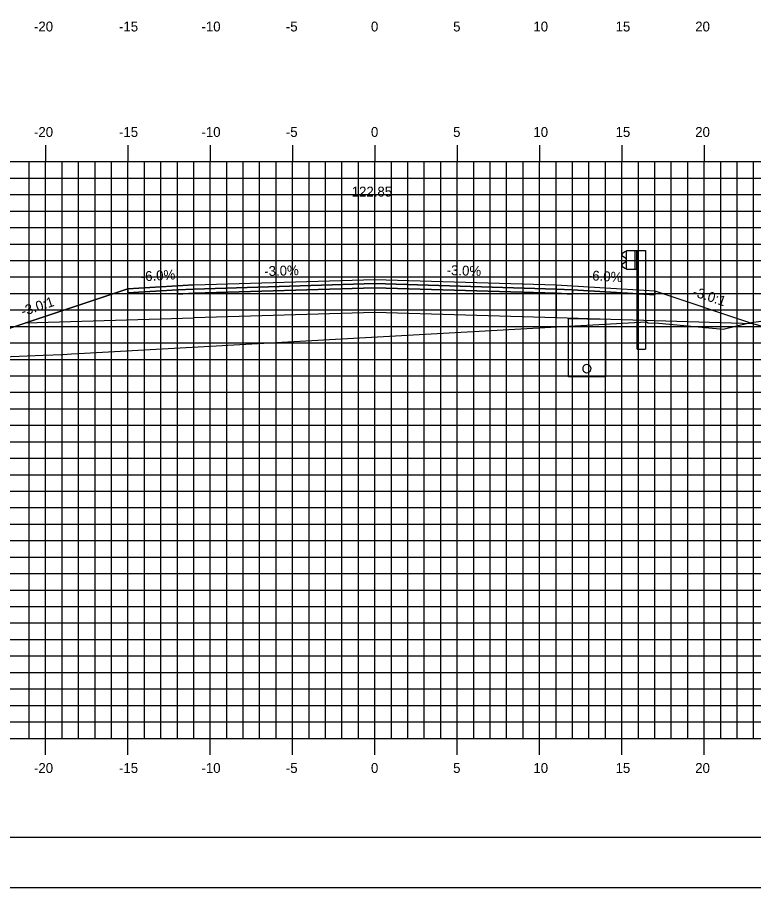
# Model space of a CAD drawing. Extents: x 850598 to 870284, y 366541 to 366651.
# Drawn here: x 855507.8 to 855552.5, y 366541.2 to 366594 of the extents above; entities that cross this region are included whole.
import ezdxf

# ---------------------------------------------------------------- set-up
doc = ezdxf.new("R2010")
doc.units = 0
for name, color, linetype in [('ANNOTATION', 7, 'Continuous'), ('BORDER', 7, 'Continuous'), ('D_Drainage_Underdrain', 7, 'Continuous'), ('D_Drainage_Underdrain_06in', 7, 'Continuous'), ('D_Guardrail_Beam_Rt', 7, 'Continuous'), ('D_Roadway_Centerline', 7, 'Continuous'), ('D_Roadway_Centerline_Text', 7, 'Continuous'), ('D_Roadway_Edge_Shoulder', 7, 'Continuous'), ('D_Roadway_Edge_TW', 7, 'Continuous'), ('D_Roadway_Pavement', 7, 'Continuous'), ('D_Roadway_SlopeLines', 7, 'Continuous'), ('D_Roadway_SubGrade', 7, 'Continuous'), ('H_V ANNOTATION', 7, 'Continuous'), ('MAJOR', 7, 'Continuous'), ('MINOR', 7, 'Continuous'), ('PLOT BOUNDARY', 7, 'Continuous'), ('S_Roadway_Centerline', 7, 'Continuous')]:
    doc.layers.add(name, color=color, linetype=linetype)

msp = doc.modelspace()

# ---------------------------------------------------------------- linework, layer by layer
at = {"layer": 'BORDER'}
msp.add_line((855484.541, 366544.225), (855644.541, 366544.225), dxfattribs=at)
at = {"layer": 'D_Drainage_Underdrain'}
msp.add_lwpolyline([(855543.541, 366575.663), (855543.541, 366572.163), (855541.291, 366572.163), (855541.291, 366575.708)], close=True, dxfattribs=at)
at = {"layer": 'D_Drainage_Underdrain_06in'}
msp.add_lwpolyline([(855542.416, 366572.913), (855542.339, 366572.901), (855542.269, 366572.865), (855542.214, 366572.81), (855542.178, 366572.74), (855542.166, 366572.663), (855542.178, 366572.586), (855542.214, 366572.516), (855542.269, 366572.461), (855542.339, 366572.425), (855542.416, 366572.413), (855542.493, 366572.425), (855542.563, 366572.461), (855542.618, 366572.516), (855542.654, 366572.586), (855542.666, 366572.663), (855542.654, 366572.74), (855542.618, 366572.81), (855542.563, 366572.865), (855542.493, 366572.901)], close=True, dxfattribs=at)
at = {"layer": 'D_Guardrail_Beam_Rt'}
for p, q in [((855544.812, 366579.764), (855544.738, 366579.751)), ((855544.812, 366579.839), (855545.499, 366579.839)), ((855544.812, 366578.672), (855544.812, 366579.839)), ((855545.333, 366579.839), (855545.333, 366578.672)), ((855545.437, 366579.839), (855545.437, 366578.672)), ((855545.499, 366579.839), (855545.97, 366579.839)), ((855545.499, 366579.839), (855545.499, 366578.672)), ((855545.97, 366579.839), (855545.97, 366573.839)), ((855544.722, 366579.745), (855544.578, 366579.645)), ((855544.578, 366579.501), (855544.774, 366579.365)), ((855544.807, 366579.301), (855544.807, 366579.21)), ((855544.774, 366579.146), (855544.578, 366579.009)), ((855544.578, 366578.866), (855544.722, 366578.766)), ((855544.738, 366578.759), (855544.812, 366578.747)), ((855545.499, 366578.672), (855544.812, 366578.672)), ((855545.478, 366573.839), (855545.478, 366578.672)), ((855545.478, 366573.839), (855545.97, 366573.839))]:
    msp.add_line(p, q, dxfattribs=at)
for centre, major_axis, start_param, end_param in [((855544.746, 366579.711), (-0.0417, 0), 4.886922, 5.323254), ((855544.629, 366579.573), (-0.0877, 0), 5.323254, 7.243116), ((855544.728, 366579.301), (0.0789, 0), 0, 0.959931), ((855544.629, 366578.938), (-0.0877, 0), 5.323254, 7.243116), ((855544.746, 366578.8), (-0.0417, 0), 0.959931, 1.396263), ((855544.728, 366579.21), (0.0789, 0), 5.323254, 6.283185)]:
    msp.add_ellipse(centre, major_axis=major_axis, ratio=0.995501, start_param=start_param, end_param=end_param, dxfattribs=at)
at = {"layer": 'D_Roadway_Centerline'}
msp.add_lwpolyline([(855501.476, 366573.15), (855504.541, 366574.172), (855508.343, 366575.439), (855514.541, 366577.505), (855518.541, 366577.745), (855529.541, 366578.075), (855540.541, 366577.745), (855544.541, 366577.505), (855546.541, 366577.385), (855552.541, 366575.385), (855599.435, 366563.225), (855612.711, 366559.783), (855622.573, 366557.225), (855626.573, 366557.225)], dxfattribs=at)
at = {"layer": 'D_Roadway_Edge_Shoulder'}
for points in [[(855518.541, 366577.745), (855514.541, 366577.505), (855514.541, 366577.255), (855517.541, 366577.435), (855518.541, 366577.495)], [(855540.541, 366577.745), (855544.541, 366577.505), (855544.541, 366577.505), (855546.541, 366577.385), (855546.541, 366577.135), (855541.541, 366577.435), (855540.541, 366577.495)]]:
    msp.add_lwpolyline(points, close=True, dxfattribs=at)
at = {"layer": 'D_Roadway_Edge_TW'}
msp.add_lwpolyline([(855518.541, 366577.495), (855518.541, 366577.745), (855529.541, 366578.075), (855540.541, 366577.745), (855540.541, 366577.495), (855529.541, 366577.825)], close=True, dxfattribs=at)
at = {"layer": 'D_Roadway_Pavement'}
for points in [[(855518.541, 366577.245), (855518.541, 366577.495), (855529.541, 366577.825), (855540.541, 366577.495), (855540.541, 366577.245), (855529.541, 366577.575)], [(855518.541, 366577.495), (855517.541, 366577.435), (855517.541, 366577.185), (855518.541, 366577.245)], [(855540.541, 366577.495), (855541.541, 366577.435), (855541.541, 366577.185), (855540.541, 366577.245)]]:
    msp.add_lwpolyline(points, close=True, dxfattribs=at)
at = {"layer": 'D_Roadway_SlopeLines'}
msp.add_lwpolyline([(855518.541, 366577.745), (855514.541, 366577.505), (855504.541, 366574.172)], dxfattribs=at)
at = {"layer": 'D_Roadway_SubGrade'}
for points in [[(855518.541, 366577.245), (855517.541, 366577.185), (855517.541, 366577.435), (855514.541, 366577.255), (855514.541, 366577.505), (855508.343, 366575.439), (855518.541, 366575.745)], [(855518.541, 366575.745), (855518.541, 366577.245), (855529.541, 366577.575), (855540.541, 366577.245), (855540.541, 366575.745), (855529.541, 366576.075)], [(855540.541, 366577.245), (855541.541, 366577.185), (855541.541, 366577.435), (855546.541, 366577.135), (855546.541, 366577.385), (855552.541, 366575.385), (855540.541, 366575.745)]]:
    msp.add_lwpolyline(points, close=True, dxfattribs=at)
at = {"layer": 'MAJOR'}
for p, q in [((855509.541, 366586.227), (855509.541, 366585.225)), ((855509.541, 366586.227), (855509.541, 366585.225)), ((855514.541, 366586.227), (855514.541, 366585.225)), ((855514.541, 366586.227), (855514.541, 366585.225)), ((855519.541, 366586.227), (855519.541, 366585.225)), ((855519.541, 366586.227), (855519.541, 366585.225)), ((855524.541, 366586.227), (855524.541, 366585.225)), ((855524.541, 366586.227), (855524.541, 366585.225)), ((855529.541, 366586.227), (855529.541, 366585.225)), ((855529.541, 366586.227), (855529.541, 366585.225)), ((855534.541, 366586.227), (855534.541, 366585.225)), ((855534.541, 366586.227), (855534.541, 366585.225)), ((855539.541, 366586.227), (855539.541, 366585.225)), ((855539.541, 366586.227), (855539.541, 366585.225)), ((855544.541, 366586.227), (855544.541, 366585.225)), ((855544.541, 366586.227), (855544.541, 366585.225)), ((855549.541, 366586.227), (855549.541, 366585.225)), ((855549.541, 366586.227), (855549.541, 366585.225)), ((855489.541, 366585.225), (855629.541, 366585.225)), ((855489.541, 366585.225), (855629.541, 366585.225)), ((855489.541, 366585.225), (855629.541, 366585.225)), ((855489.541, 366585.225), (855629.541, 366585.225)), ((855509.541, 366550.225), (855509.541, 366585.225)), ((855509.541, 366550.225), (855509.541, 366585.225)), ((855514.541, 366550.225), (855514.541, 366585.225)), ((855514.541, 366550.225), (855514.541, 366585.225)), ((855519.541, 366550.225), (855519.541, 366585.225)), ((855519.541, 366550.225), (855519.541, 366585.225)), ((855524.541, 366550.225), (855524.541, 366585.225)), ((855524.541, 366550.225), (855524.541, 366585.225)), ((855529.541, 366550.225), (855529.541, 366585.225)), ((855529.541, 366550.225), (855529.541, 366585.225)), ((855534.541, 366550.225), (855534.541, 366585.225)), ((855534.541, 366550.225), (855534.541, 366585.225)), ((855539.541, 366550.225), (855539.541, 366585.225)), ((855539.541, 366550.225), (855539.541, 366585.225)), ((855544.541, 366550.225), (855544.541, 366585.225)), ((855544.541, 366550.225), (855544.541, 366585.225)), ((855549.541, 366550.225), (855549.541, 366585.225)), ((855549.541, 366550.225), (855549.541, 366585.225)), ((855489.541, 366580.225), (855629.541, 366580.225)), ((855489.541, 366580.225), (855629.541, 366580.225)), ((855489.541, 366575.225), (855629.541, 366575.225)), ((855489.541, 366575.225), (855629.541, 366575.225)), ((855489.541, 366570.225), (855629.541, 366570.225)), ((855489.541, 366570.225), (855629.541, 366570.225)), ((855489.541, 366565.225), (855629.541, 366565.225)), ((855489.541, 366565.225), (855629.541, 366565.225)), ((855489.541, 366560.225), (855629.541, 366560.225)), ((855489.541, 366560.225), (855629.541, 366560.225)), ((855489.541, 366555.225), (855629.541, 366555.225)), ((855489.541, 366555.225), (855629.541, 366555.225)), ((855489.541, 366550.225), (855629.541, 366550.225)), ((855489.541, 366550.225), (855629.541, 366550.225)), ((855489.541, 366550.225), (855629.541, 366550.225)), ((855489.541, 366550.225), (855629.541, 366550.225)), ((855509.541, 366549.223), (855509.541, 366550.225)), ((855509.541, 366549.223), (855509.541, 366550.225)), ((855514.541, 366549.223), (855514.541, 366550.225)), ((855514.541, 366549.223), (855514.541, 366550.225)), ((855519.541, 366549.223), (855519.541, 366550.225)), ((855519.541, 366549.223), (855519.541, 366550.225)), ((855524.541, 366549.223), (855524.541, 366550.225)), ((855524.541, 366549.223), (855524.541, 366550.225)), ((855529.541, 366549.223), (855529.541, 366550.225)), ((855529.541, 366549.223), (855529.541, 366550.225)), ((855534.541, 366549.223), (855534.541, 366550.225)), ((855534.541, 366549.223), (855534.541, 366550.225)), ((855539.541, 366549.223), (855539.541, 366550.225)), ((855539.541, 366549.223), (855539.541, 366550.225)), ((855544.541, 366549.223), (855544.541, 366550.225)), ((855544.541, 366549.223), (855544.541, 366550.225)), ((855549.541, 366549.223), (855549.541, 366550.225)), ((855549.541, 366549.223), (855549.541, 366550.225))]:
    msp.add_line(p, q, dxfattribs=at)
at = {"layer": 'MINOR'}
for p, q in [((855508.541, 366550.225), (855508.541, 366585.225)), ((855508.541, 366550.225), (855508.541, 366585.225)), ((855510.541, 366550.225), (855510.541, 366585.225)), ((855510.541, 366550.225), (855510.541, 366585.225)), ((855511.541, 366550.225), (855511.541, 366585.225)), ((855511.541, 366550.225), (855511.541, 366585.225)), ((855512.541, 366550.225), (855512.541, 366585.225)), ((855512.541, 366550.225), (855512.541, 366585.225)), ((855513.541, 366550.225), (855513.541, 366585.225)), ((855513.541, 366550.225), (855513.541, 366585.225)), ((855515.541, 366550.225), (855515.541, 366585.225)), ((855515.541, 366550.225), (855515.541, 366585.225)), ((855516.541, 366550.225), (855516.541, 366585.225)), ((855516.541, 366550.225), (855516.541, 366585.225)), ((855517.541, 366550.225), (855517.541, 366585.225)), ((855517.541, 366550.225), (855517.541, 366585.225)), ((855518.541, 366550.225), (855518.541, 366585.225)), ((855518.541, 366550.225), (855518.541, 366585.225)), ((855520.541, 366550.225), (855520.541, 366585.225)), ((855520.541, 366550.225), (855520.541, 366585.225)), ((855521.541, 366550.225), (855521.541, 366585.225)), ((855521.541, 366550.225), (855521.541, 366585.225)), ((855522.541, 366550.225), (855522.541, 366585.225)), ((855522.541, 366550.225), (855522.541, 366585.225)), ((855523.541, 366550.225), (855523.541, 366585.225)), ((855523.541, 366550.225), (855523.541, 366585.225)), ((855525.541, 366550.225), (855525.541, 366585.225)), ((855525.541, 366550.225), (855525.541, 366585.225)), ((855526.541, 366550.225), (855526.541, 366585.225)), ((855526.541, 366550.225), (855526.541, 366585.225)), ((855527.541, 366550.225), (855527.541, 366585.225)), ((855527.541, 366550.225), (855527.541, 366585.225)), ((855528.541, 366550.225), (855528.541, 366585.225)), ((855528.541, 366550.225), (855528.541, 366585.225)), ((855530.541, 366550.225), (855530.541, 366585.225)), ((855530.541, 366550.225), (855530.541, 366585.225)), ((855531.541, 366550.225), (855531.541, 366585.225)), ((855531.541, 366550.225), (855531.541, 366585.225)), ((855532.541, 366550.225), (855532.541, 366585.225)), ((855532.541, 366550.225), (855532.541, 366585.225)), ((855533.541, 366550.225), (855533.541, 366585.225)), ((855533.541, 366550.225), (855533.541, 366585.225)), ((855535.541, 366550.225), (855535.541, 366585.225)), ((855535.541, 366550.225), (855535.541, 366585.225)), ((855536.541, 366550.225), (855536.541, 366585.225)), ((855536.541, 366550.225), (855536.541, 366585.225)), ((855537.541, 366550.225), (855537.541, 366585.225)), ((855537.541, 366550.225), (855537.541, 366585.225)), ((855538.541, 366550.225), (855538.541, 366585.225)), ((855538.541, 366550.225), (855538.541, 366585.225)), ((855540.541, 366550.225), (855540.541, 366585.225)), ((855540.541, 366550.225), (855540.541, 366585.225)), ((855541.541, 366550.225), (855541.541, 366585.225)), ((855541.541, 366550.225), (855541.541, 366585.225)), ((855542.541, 366550.225), (855542.541, 366585.225)), ((855542.541, 366550.225), (855542.541, 366585.225)), ((855543.541, 366550.225), (855543.541, 366585.225)), ((855543.541, 366550.225), (855543.541, 366585.225)), ((855545.541, 366550.225), (855545.541, 366585.225)), ((855545.541, 366550.225), (855545.541, 366585.225)), ((855546.541, 366550.225), (855546.541, 366585.225)), ((855546.541, 366550.225), (855546.541, 366585.225)), ((855547.541, 366550.225), (855547.541, 366585.225)), ((855547.541, 366550.225), (855547.541, 366585.225)), ((855548.541, 366550.225), (855548.541, 366585.225)), ((855548.541, 366550.225), (855548.541, 366585.225)), ((855550.541, 366550.225), (855550.541, 366585.225)), ((855550.541, 366550.225), (855550.541, 366585.225)), ((855551.541, 366550.225), (855551.541, 366585.225)), ((855551.541, 366550.225), (855551.541, 366585.225)), ((855552.541, 366550.225), (855552.541, 366585.225)), ((855552.541, 366550.225), (855552.541, 366585.225)), ((855489.541, 366584.225), (855629.541, 366584.225)), ((855489.541, 366584.225), (855629.541, 366584.225)), ((855489.541, 366583.225), (855629.541, 366583.225)), ((855489.541, 366583.225), (855629.541, 366583.225)), ((855489.541, 366582.225), (855629.541, 366582.225)), ((855489.541, 366582.225), (855629.541, 366582.225)), ((855489.541, 366581.225), (855629.541, 366581.225)), ((855489.541, 366581.225), (855629.541, 366581.225)), ((855489.541, 366579.225), (855629.541, 366579.225)), ((855489.541, 366579.225), (855629.541, 366579.225)), ((855489.541, 366578.225), (855629.541, 366578.225)), ((855489.541, 366578.225), (855629.541, 366578.225)), ((855489.541, 366577.225), (855629.541, 366577.225)), ((855489.541, 366577.225), (855629.541, 366577.225)), ((855489.541, 366576.225), (855629.541, 366576.225)), ((855489.541, 366576.225), (855629.541, 366576.225)), ((855489.541, 366574.225), (855629.541, 366574.225)), ((855489.541, 366574.225), (855629.541, 366574.225)), ((855489.541, 366573.225), (855629.541, 366573.225)), ((855489.541, 366573.225), (855629.541, 366573.225)), ((855489.541, 366572.225), (855629.541, 366572.225)), ((855489.541, 366572.225), (855629.541, 366572.225)), ((855489.541, 366571.225), (855629.541, 366571.225)), ((855489.541, 366571.225), (855629.541, 366571.225)), ((855489.541, 366569.225), (855629.541, 366569.225)), ((855489.541, 366569.225), (855629.541, 366569.225)), ((855489.541, 366568.225), (855629.541, 366568.225)), ((855489.541, 366568.225), (855629.541, 366568.225)), ((855489.541, 366567.225), (855629.541, 366567.225)), ((855489.541, 366567.225), (855629.541, 366567.225)), ((855489.541, 366566.225), (855629.541, 366566.225)), ((855489.541, 366566.225), (855629.541, 366566.225)), ((855489.541, 366564.225), (855629.541, 366564.225)), ((855489.541, 366564.225), (855629.541, 366564.225)), ((855489.541, 366563.225), (855629.541, 366563.225)), ((855489.541, 366563.225), (855629.541, 366563.225)), ((855489.541, 366562.225), (855629.541, 366562.225)), ((855489.541, 366562.225), (855629.541, 366562.225)), ((855489.541, 366561.225), (855629.541, 366561.225)), ((855489.541, 366561.225), (855629.541, 366561.225)), ((855489.541, 366559.225), (855629.541, 366559.225)), ((855489.541, 366559.225), (855629.541, 366559.225)), ((855489.541, 366558.225), (855629.541, 366558.225)), ((855489.541, 366558.225), (855629.541, 366558.225)), ((855489.541, 366557.225), (855629.541, 366557.225)), ((855489.541, 366557.225), (855629.541, 366557.225)), ((855489.541, 366556.225), (855629.541, 366556.225)), ((855489.541, 366556.225), (855629.541, 366556.225)), ((855489.541, 366554.225), (855629.541, 366554.225)), ((855489.541, 366554.225), (855629.541, 366554.225)), ((855489.541, 366553.225), (855629.541, 366553.225)), ((855489.541, 366553.225), (855629.541, 366553.225)), ((855489.541, 366552.225), (855629.541, 366552.225)), ((855489.541, 366552.225), (855629.541, 366552.225)), ((855489.541, 366551.225), (855629.541, 366551.225)), ((855489.541, 366551.225), (855629.541, 366551.225))]:
    msp.add_line(p, q, dxfattribs=at)
at = {"layer": 'PLOT BOUNDARY'}
msp.add_lwpolyline([(855476.448, 366541.166), (855646.448, 366541.166), (855646.448, 366651.166), (855476.448, 366651.166)], close=True, dxfattribs=at)
at = {"layer": 'S_Roadway_Centerline'}
msp.add_lwpolyline([(855489.541, 366572.658), (855509.391, 366573.477), (855510.587, 366573.525), (855511.107, 366573.553), (855511.902, 366573.599), (855546.029, 366575.505), (855546.128, 366575.452), (855546.789, 366575.431), (855550.688, 366575.062), (855552.268, 366575.452), (855555.684, 366575.937), (855558.473, 366576.523), (855559.25, 366576.631), (855562.281, 366576.772), (855574.239, 366577.27), (855584.225, 366576.836), (855596.978, 366576.213), (855597.334, 366576.137), (855599.725, 366575.467), (855603.412, 366572.497), (855616.858, 366561.048), (855629.541, 366556.057)], dxfattribs=at)

# ---------------------------------------------------------------- texts
at = {"layer": 'ANNOTATION'}
for s, rotation, p in [('-3.0%', 1.7184, (855522.829, 366578.275)), ('-3.0%', 358.2816, (855533.889, 366578.345)), ('-6.0%', 3.4336, (855515.338, 366577.955)), ('-6.0%', 356.5664, (855542.458, 366578.032)), ('-3.0:1', 341.5651, (855548.795, 366577.088)), ('-3.0:1', 18.4348, (855508.162, 366575.833))]:
    msp.add_text(s, height=0.6, rotation=rotation, dxfattribs=at).set_placement(p)
at = {"layer": 'D_Roadway_Centerline'}
for s, p in [('C', (855529.536, 366578.075)), ('C', (855529.536, 366578.075)), ('L', (855529.541, 366578.068)), ('L', (855529.541, 366578.068))]:
    msp.add_text(s, height=0.0146, dxfattribs=at).set_placement(p)
at = {"layer": 'D_Roadway_Centerline_Text'}
msp.add_text('122.85', height=0.6, dxfattribs=at).set_placement((855528.131, 366583.107))
at = {"layer": 'H_V ANNOTATION'}
for s, p in [('-20', (855508.834, 366593.125)), ('-15', (855513.998, 366593.125)), ('-10', (855519.006, 366593.125)), ('-5', (855524.131, 366593.125)), ('0', (855529.3, 366593.125)), ('5', (855534.292, 366593.125)), ('10', (855539.166, 366593.125)), ('15', (855544.158, 366593.125)), ('20', (855548.995, 366593.125)), ('-20', (855508.834, 366586.725)), ('-15', (855513.998, 366586.725)), ('-10', (855519.006, 366586.725)), ('-5', (855524.131, 366586.725)), ('0', (855529.3, 366586.725)), ('5', (855534.292, 366586.725)), ('10', (855539.166, 366586.725)), ('15', (855544.158, 366586.725)), ('20', (855548.995, 366586.725)), ('-20', (855508.834, 366548.125)), ('-15', (855513.998, 366548.125)), ('-10', (855519.006, 366548.125)), ('-5', (855524.131, 366548.125)), ('0', (855529.3, 366548.125)), ('5', (855534.292, 366548.125)), ('10', (855539.166, 366548.125)), ('15', (855544.158, 366548.125)), ('20', (855548.995, 366548.125))]:
    msp.add_text(s, height=0.6, dxfattribs=at).set_placement(p)

doc.saveas('drawing.dxf')
